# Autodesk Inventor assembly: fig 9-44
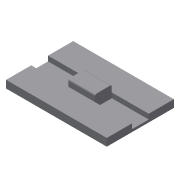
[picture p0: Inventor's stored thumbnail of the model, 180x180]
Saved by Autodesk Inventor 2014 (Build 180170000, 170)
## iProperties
Created: 2013-07
Part Number: fig 9-44
Document SubType Name: Assembly
Designer: CADCIM
Author: CADCIM
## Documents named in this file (3)
- E:\APS\Autodesk Inventor 2014-Project\inventor_2014_partfiles\Inventor_2014_prt\c09_Inv_2014_prt\c09_inv_2014_prt\fig 9-44.iam
- E:\APS\Autodesk Inventor 2014-Project\inventor_2014_partfiles\Inventor_2014_prt\c09_Inv_2014_prt\c09_inv_2014_prt\15.ipt
- E:\APS\Autodesk Inventor 2014-Project\inventor_2014_partfiles\Inventor_2014_prt\c09_Inv_2014_prt\c09_inv_2014_prt\16.ipt
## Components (2 placed, 2 different names)
1. 15:1 — Slider:1
2. 16:1 — Slider:1
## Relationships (1: TranslationJoint 1)
- Slider:1 [TranslationJoint]: 15:1 ↔ 16:1
